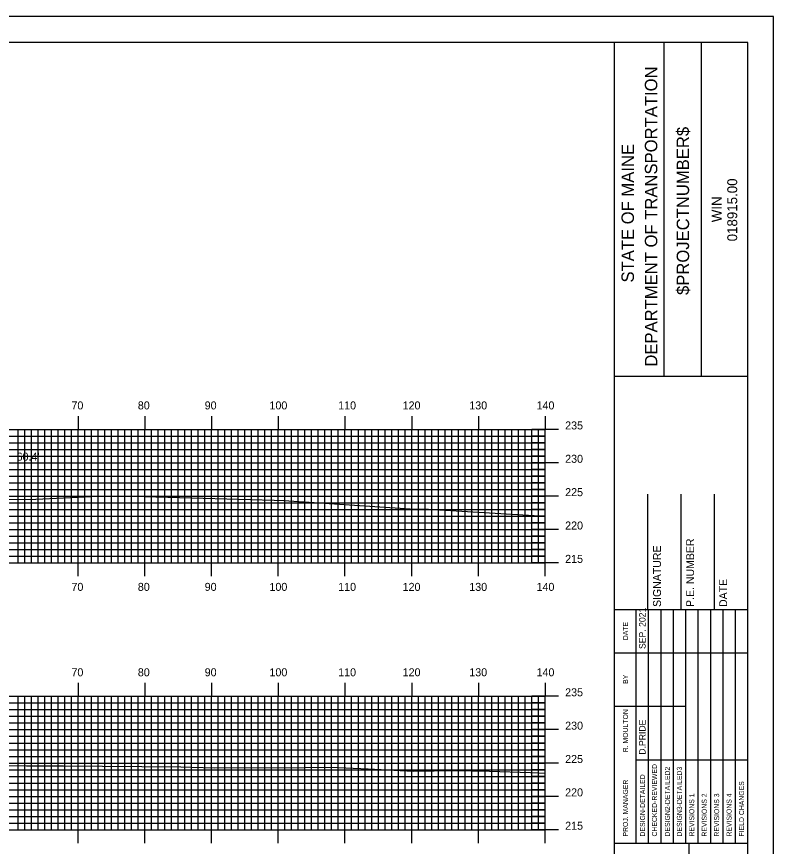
# Model space of a CAD drawing. Extents: x 1804684 to 1805027, y 442591 to 442811.
# Drawn here: x 1804910.5 to 1805023.9, y 442686.2 to 442810.5 of the extents above; entities that cross this region are included whole.
import ezdxf

# ---------------------------------------------------------------- set-up
doc = ezdxf.new("R2010")
doc.units = 0
for name, color, linetype in [('BORDER', 7, 'Continuous'), ('D_Text_Standard', 7, 'Continuous'), ('H_V ANNOTATION', 7, 'Continuous'), ('MAJOR', 7, 'Continuous'), ('MINOR', 7, 'Continuous'), ('PLOT BOUNDARY', 7, 'Continuous'), ('S_Roadway_Centerline', 7, 'Continuous')]:
    doc.layers.add(name, color=color, linetype=linetype)

msp = doc.modelspace()

# ---------------------------------------------------------------- linework, layer by layer
at = {"layer": 'BORDER'}
for p, q in [((1805000.08, 442596.67), (1805000.08, 442806.67)), ((1805007.54, 442756.66), (1805007.54, 442806.66)), ((1805013.13, 442756.66), (1805013.13, 442806.66)), ((1805000.08, 442756.65), (1805020.08, 442756.65)), ((1805005.08, 442721.67), (1805005.08, 442738.97)), ((1805010.08, 442721.67), (1805010.08, 442738.97)), ((1805015.08, 442721.67), (1805015.08, 442738.97)), ((1805000.08, 442721.67), (1805020.08, 442721.67)), ((1805000.08, 442686.67), (1805020.08, 442686.67)), ((1805011.26, 442616.67), (1805011.26, 442686.67))]:
    msp.add_line(p, q, dxfattribs=at)
msp.add_lwpolyline([(1804700.08, 442596.67), (1805020.08, 442596.67), (1805020.08, 442806.67), (1804700.08, 442806.67)], close=True, dxfattribs=at)
for points in [[(1805003.31, 442715.17), (1805003.31, 442721.67)], [(1805005.18, 442686.68), (1805005.18, 442721.67)], [(1805007.04, 442721.67), (1805007.04, 442686.68)], [(1805008.9, 442686.68), (1805008.9, 442721.67)], [(1805010.77, 442686.68), (1805010.77, 442721.67)], [(1805012.63, 442686.68), (1805012.63, 442721.67)], [(1805014.49, 442686.68), (1805014.49, 442721.67)], [(1805016.36, 442686.68), (1805016.36, 442721.67)], [(1805018.22, 442686.68), (1805018.22, 442721.67)], [(1805003.31, 442686.68), (1805003.31, 442720.26)], [(1805000.08, 442715.17), (1805020.08, 442715.17)], [(1805000.08, 442707.17), (1805003.31, 442707.17)], [(1805003.31, 442707.17), (1805010.76, 442707.17)], [(1805003.31, 442699.17), (1805020.08, 442699.17)]]:
    msp.add_lwpolyline(points, dxfattribs=at)
at = {"layer": 'MAJOR'}
for p, q in [((1804919.68, 442750.67), (1804919.68, 442748.67)), ((1804929.68, 442750.67), (1804929.68, 442748.67)), ((1804939.68, 442750.67), (1804939.68, 442748.67)), ((1804949.68, 442750.67), (1804949.68, 442748.67)), ((1804959.68, 442750.67), (1804959.68, 442748.67)), ((1804969.68, 442750.67), (1804969.68, 442748.67)), ((1804979.68, 442750.67), (1804979.68, 442748.67)), ((1804989.68, 442750.67), (1804989.68, 442748.67)), ((1804709.68, 442748.67), (1804989.68, 442748.67)), ((1804709.68, 442748.67), (1804989.68, 442748.67)), ((1804919.68, 442728.67), (1804919.68, 442748.67)), ((1804929.68, 442728.67), (1804929.68, 442748.67)), ((1804939.68, 442728.67), (1804939.68, 442748.67)), ((1804949.68, 442728.67), (1804949.68, 442748.67)), ((1804959.68, 442728.67), (1804959.68, 442748.67)), ((1804969.68, 442728.67), (1804969.68, 442748.67)), ((1804979.68, 442728.67), (1804979.68, 442748.67)), ((1804991.68, 442748.67), (1804987.68, 442748.67)), ((1804989.68, 442728.67), (1804989.68, 442748.67)), ((1804989.68, 442728.67), (1804989.68, 442748.67)), ((1804709.68, 442743.67), (1804989.68, 442743.67)), ((1804991.68, 442743.67), (1804987.68, 442743.67)), ((1804709.68, 442738.67), (1804989.68, 442738.67)), ((1804991.68, 442738.67), (1804987.68, 442738.67)), ((1804709.68, 442733.67), (1804989.68, 442733.67)), ((1804991.68, 442733.67), (1804987.68, 442733.67)), ((1804709.68, 442728.67), (1804989.68, 442728.67)), ((1804709.68, 442728.67), (1804989.68, 442728.67)), ((1804919.68, 442726.66), (1804919.68, 442728.67)), ((1804929.68, 442726.66), (1804929.68, 442728.67)), ((1804939.68, 442726.66), (1804939.68, 442728.67)), ((1804949.68, 442726.66), (1804949.68, 442728.67)), ((1804959.68, 442726.66), (1804959.68, 442728.67)), ((1804969.68, 442726.66), (1804969.68, 442728.67)), ((1804979.68, 442726.66), (1804979.68, 442728.67)), ((1804991.68, 442728.67), (1804987.68, 442728.67)), ((1804989.68, 442726.66), (1804989.68, 442728.67)), ((1804919.68, 442710.67), (1804919.68, 442708.67)), ((1804929.68, 442710.67), (1804929.68, 442708.67)), ((1804939.68, 442710.67), (1804939.68, 442708.67)), ((1804949.68, 442710.67), (1804949.68, 442708.67)), ((1804959.68, 442710.67), (1804959.68, 442708.67)), ((1804969.68, 442710.67), (1804969.68, 442708.67)), ((1804979.68, 442710.67), (1804979.68, 442708.67)), ((1804989.68, 442710.67), (1804989.68, 442708.67)), ((1804709.68, 442708.67), (1804989.68, 442708.67)), ((1804709.68, 442708.67), (1804989.68, 442708.67)), ((1804919.68, 442688.67), (1804919.68, 442708.67)), ((1804929.68, 442688.67), (1804929.68, 442708.67)), ((1804939.68, 442688.67), (1804939.68, 442708.67)), ((1804949.68, 442688.67), (1804949.68, 442708.67)), ((1804959.68, 442688.67), (1804959.68, 442708.67)), ((1804969.68, 442688.67), (1804969.68, 442708.67)), ((1804979.68, 442688.67), (1804979.68, 442708.67)), ((1804991.68, 442708.67), (1804987.68, 442708.67)), ((1804989.68, 442688.67), (1804989.68, 442708.67)), ((1804989.68, 442688.67), (1804989.68, 442708.67)), ((1804709.68, 442703.67), (1804989.68, 442703.67)), ((1804991.68, 442703.67), (1804987.68, 442703.67)), ((1804709.68, 442698.67), (1804989.68, 442698.67)), ((1804991.68, 442698.67), (1804987.68, 442698.67)), ((1804709.68, 442693.67), (1804989.68, 442693.67)), ((1804991.68, 442693.67), (1804987.68, 442693.67)), ((1804709.68, 442688.67), (1804989.68, 442688.67)), ((1804709.68, 442688.67), (1804989.68, 442688.67)), ((1804919.68, 442686.66), (1804919.68, 442688.67)), ((1804929.68, 442686.66), (1804929.68, 442688.67)), ((1804939.68, 442686.66), (1804939.68, 442688.67)), ((1804949.68, 442686.66), (1804949.68, 442688.67)), ((1804959.68, 442686.66), (1804959.68, 442688.67)), ((1804969.68, 442686.66), (1804969.68, 442688.67)), ((1804979.68, 442686.66), (1804979.68, 442688.67)), ((1804991.68, 442688.67), (1804987.68, 442688.67)), ((1804989.68, 442686.66), (1804989.68, 442688.67))]:
    msp.add_line(p, q, dxfattribs=at)
at = {"layer": 'MINOR'}
for p, q in [((1804910.68, 442728.67), (1804910.68, 442748.67)), ((1804911.68, 442728.67), (1804911.68, 442748.67)), ((1804912.68, 442728.67), (1804912.68, 442748.67)), ((1804913.68, 442728.67), (1804913.68, 442748.67)), ((1804914.68, 442728.67), (1804914.68, 442748.67)), ((1804915.68, 442728.67), (1804915.68, 442748.67)), ((1804916.68, 442728.67), (1804916.68, 442748.67)), ((1804917.68, 442728.67), (1804917.68, 442748.67)), ((1804918.68, 442728.67), (1804918.68, 442748.67)), ((1804920.68, 442728.67), (1804920.68, 442748.67)), ((1804921.68, 442728.67), (1804921.68, 442748.67)), ((1804922.68, 442728.67), (1804922.68, 442748.67)), ((1804923.68, 442728.67), (1804923.68, 442748.67)), ((1804924.68, 442728.67), (1804924.68, 442748.67)), ((1804925.68, 442728.67), (1804925.68, 442748.67)), ((1804926.68, 442728.67), (1804926.68, 442748.67)), ((1804927.68, 442728.67), (1804927.68, 442748.67)), ((1804928.68, 442728.67), (1804928.68, 442748.67)), ((1804930.68, 442728.67), (1804930.68, 442748.67)), ((1804931.68, 442728.67), (1804931.68, 442748.67)), ((1804932.68, 442728.67), (1804932.68, 442748.67)), ((1804933.68, 442728.67), (1804933.68, 442748.67)), ((1804934.68, 442728.67), (1804934.68, 442748.67)), ((1804935.68, 442728.67), (1804935.68, 442748.67)), ((1804936.68, 442728.67), (1804936.68, 442748.67)), ((1804937.68, 442728.67), (1804937.68, 442748.67)), ((1804938.68, 442728.67), (1804938.68, 442748.67)), ((1804940.68, 442728.67), (1804940.68, 442748.67)), ((1804941.68, 442728.67), (1804941.68, 442748.67)), ((1804942.68, 442728.67), (1804942.68, 442748.67)), ((1804943.68, 442728.67), (1804943.68, 442748.67)), ((1804944.68, 442728.67), (1804944.68, 442748.67)), ((1804945.68, 442728.67), (1804945.68, 442748.67)), ((1804946.68, 442728.67), (1804946.68, 442748.67)), ((1804947.68, 442728.67), (1804947.68, 442748.67)), ((1804948.68, 442728.67), (1804948.68, 442748.67)), ((1804950.68, 442728.67), (1804950.68, 442748.67)), ((1804951.68, 442728.67), (1804951.68, 442748.67)), ((1804952.68, 442728.67), (1804952.68, 442748.67)), ((1804953.68, 442728.67), (1804953.68, 442748.67)), ((1804954.68, 442728.67), (1804954.68, 442748.67)), ((1804955.68, 442728.67), (1804955.68, 442748.67)), ((1804956.68, 442728.67), (1804956.68, 442748.67)), ((1804957.68, 442728.67), (1804957.68, 442748.67)), ((1804958.68, 442728.67), (1804958.68, 442748.67)), ((1804960.68, 442728.67), (1804960.68, 442748.67)), ((1804961.68, 442728.67), (1804961.68, 442748.67)), ((1804962.68, 442728.67), (1804962.68, 442748.67)), ((1804963.68, 442728.67), (1804963.68, 442748.67)), ((1804964.68, 442728.67), (1804964.68, 442748.67)), ((1804965.68, 442728.67), (1804965.68, 442748.67)), ((1804966.68, 442728.67), (1804966.68, 442748.67)), ((1804967.68, 442728.67), (1804967.68, 442748.67)), ((1804968.68, 442728.67), (1804968.68, 442748.67)), ((1804970.68, 442728.67), (1804970.68, 442748.67)), ((1804971.68, 442728.67), (1804971.68, 442748.67)), ((1804972.68, 442728.67), (1804972.68, 442748.67)), ((1804973.68, 442728.67), (1804973.68, 442748.67)), ((1804974.68, 442728.67), (1804974.68, 442748.67)), ((1804975.68, 442728.67), (1804975.68, 442748.67)), ((1804976.68, 442728.67), (1804976.68, 442748.67)), ((1804977.68, 442728.67), (1804977.68, 442748.67)), ((1804978.68, 442728.67), (1804978.68, 442748.67)), ((1804980.68, 442728.67), (1804980.68, 442748.67)), ((1804981.68, 442728.67), (1804981.68, 442748.67)), ((1804982.68, 442728.67), (1804982.68, 442748.67)), ((1804983.68, 442728.67), (1804983.68, 442748.67)), ((1804984.68, 442728.67), (1804984.68, 442748.67)), ((1804985.68, 442728.67), (1804985.68, 442748.67)), ((1804986.68, 442728.67), (1804986.68, 442748.67)), ((1804987.68, 442728.67), (1804987.68, 442748.67)), ((1804988.68, 442728.67), (1804988.68, 442748.67)), ((1804709.68, 442747.67), (1804989.68, 442747.67)), ((1804989.68, 442747.67), (1804987.68, 442747.67)), ((1804709.68, 442746.67), (1804989.68, 442746.67)), ((1804709.68, 442745.67), (1804989.68, 442745.67)), ((1804989.68, 442746.67), (1804987.68, 442746.67)), ((1804989.68, 442745.67), (1804987.68, 442745.67)), ((1804709.68, 442744.67), (1804989.68, 442744.67)), ((1804989.68, 442744.67), (1804987.68, 442744.67)), ((1804709.68, 442742.67), (1804989.68, 442742.67)), ((1804989.68, 442742.67), (1804987.68, 442742.67)), ((1804709.68, 442741.67), (1804989.68, 442741.67)), ((1804709.68, 442740.67), (1804989.68, 442740.67)), ((1804989.68, 442741.67), (1804987.68, 442741.67)), ((1804989.68, 442740.67), (1804987.68, 442740.67)), ((1804709.68, 442739.67), (1804989.68, 442739.67)), ((1804989.68, 442739.67), (1804987.68, 442739.67)), ((1804709.68, 442737.67), (1804989.68, 442737.67)), ((1804989.68, 442737.67), (1804987.68, 442737.67)), ((1804709.68, 442736.67), (1804989.68, 442736.67)), ((1804709.68, 442735.67), (1804989.68, 442735.67)), ((1804989.68, 442736.67), (1804987.68, 442736.67)), ((1804989.68, 442735.67), (1804987.68, 442735.67)), ((1804709.68, 442734.67), (1804989.68, 442734.67)), ((1804989.68, 442734.67), (1804987.68, 442734.67)), ((1804709.68, 442732.67), (1804989.68, 442732.67)), ((1804989.68, 442732.67), (1804987.68, 442732.67)), ((1804709.68, 442731.67), (1804989.68, 442731.67)), ((1804709.68, 442730.67), (1804989.68, 442730.67)), ((1804989.68, 442731.67), (1804987.68, 442731.67)), ((1804989.68, 442730.67), (1804987.68, 442730.67)), ((1804709.68, 442729.67), (1804989.68, 442729.67)), ((1804989.68, 442729.67), (1804987.68, 442729.67)), ((1804910.68, 442688.67), (1804910.68, 442708.67)), ((1804911.68, 442688.67), (1804911.68, 442708.67)), ((1804912.68, 442688.67), (1804912.68, 442708.67)), ((1804913.68, 442688.67), (1804913.68, 442708.67)), ((1804914.68, 442688.67), (1804914.68, 442708.67)), ((1804915.68, 442688.67), (1804915.68, 442708.67)), ((1804916.68, 442688.67), (1804916.68, 442708.67)), ((1804917.68, 442688.67), (1804917.68, 442708.67)), ((1804918.68, 442688.67), (1804918.68, 442708.67)), ((1804920.68, 442688.67), (1804920.68, 442708.67)), ((1804921.68, 442688.67), (1804921.68, 442708.67)), ((1804922.68, 442688.67), (1804922.68, 442708.67)), ((1804923.68, 442688.67), (1804923.68, 442708.67)), ((1804924.68, 442688.67), (1804924.68, 442708.67)), ((1804925.68, 442688.67), (1804925.68, 442708.67)), ((1804926.68, 442688.67), (1804926.68, 442708.67)), ((1804927.68, 442688.67), (1804927.68, 442708.67)), ((1804928.68, 442688.67), (1804928.68, 442708.67)), ((1804930.68, 442688.67), (1804930.68, 442708.67)), ((1804931.68, 442688.67), (1804931.68, 442708.67)), ((1804932.68, 442688.67), (1804932.68, 442708.67)), ((1804933.68, 442688.67), (1804933.68, 442708.67)), ((1804934.68, 442688.67), (1804934.68, 442708.67)), ((1804935.68, 442688.67), (1804935.68, 442708.67)), ((1804936.68, 442688.67), (1804936.68, 442708.67)), ((1804937.68, 442688.67), (1804937.68, 442708.67)), ((1804938.68, 442688.67), (1804938.68, 442708.67)), ((1804940.68, 442688.67), (1804940.68, 442708.67)), ((1804941.68, 442688.67), (1804941.68, 442708.67)), ((1804942.68, 442688.67), (1804942.68, 442708.67)), ((1804943.68, 442688.67), (1804943.68, 442708.67)), ((1804944.68, 442688.67), (1804944.68, 442708.67)), ((1804945.68, 442688.67), (1804945.68, 442708.67)), ((1804946.68, 442688.67), (1804946.68, 442708.67)), ((1804947.68, 442688.67), (1804947.68, 442708.67)), ((1804948.68, 442688.67), (1804948.68, 442708.67)), ((1804950.68, 442688.67), (1804950.68, 442708.67)), ((1804951.68, 442688.67), (1804951.68, 442708.67)), ((1804952.68, 442688.67), (1804952.68, 442708.67)), ((1804953.68, 442688.67), (1804953.68, 442708.67)), ((1804954.68, 442688.67), (1804954.68, 442708.67)), ((1804955.68, 442688.67), (1804955.68, 442708.67)), ((1804956.68, 442688.67), (1804956.68, 442708.67)), ((1804957.68, 442688.67), (1804957.68, 442708.67)), ((1804958.68, 442688.67), (1804958.68, 442708.67)), ((1804960.68, 442688.67), (1804960.68, 442708.67)), ((1804961.68, 442688.67), (1804961.68, 442708.67)), ((1804962.68, 442688.67), (1804962.68, 442708.67)), ((1804963.68, 442688.67), (1804963.68, 442708.67)), ((1804964.68, 442688.67), (1804964.68, 442708.67)), ((1804965.68, 442688.67), (1804965.68, 442708.67)), ((1804966.68, 442688.67), (1804966.68, 442708.67)), ((1804967.68, 442688.67), (1804967.68, 442708.67)), ((1804968.68, 442688.67), (1804968.68, 442708.67)), ((1804970.68, 442688.67), (1804970.68, 442708.67)), ((1804971.68, 442688.67), (1804971.68, 442708.67)), ((1804972.68, 442688.67), (1804972.68, 442708.67)), ((1804973.68, 442688.67), (1804973.68, 442708.67)), ((1804974.68, 442688.67), (1804974.68, 442708.67)), ((1804975.68, 442688.67), (1804975.68, 442708.67)), ((1804976.68, 442688.67), (1804976.68, 442708.67)), ((1804977.68, 442688.67), (1804977.68, 442708.67)), ((1804978.68, 442688.67), (1804978.68, 442708.67)), ((1804980.68, 442688.67), (1804980.68, 442708.67)), ((1804981.68, 442688.67), (1804981.68, 442708.67)), ((1804982.68, 442688.67), (1804982.68, 442708.67)), ((1804983.68, 442688.67), (1804983.68, 442708.67)), ((1804984.68, 442688.67), (1804984.68, 442708.67)), ((1804985.68, 442688.67), (1804985.68, 442708.67)), ((1804986.68, 442688.67), (1804986.68, 442708.67)), ((1804987.68, 442688.67), (1804987.68, 442708.67)), ((1804988.68, 442688.67), (1804988.68, 442708.67)), ((1804709.68, 442707.67), (1804989.68, 442707.67)), ((1804989.68, 442707.67), (1804987.68, 442707.67)), ((1804709.68, 442706.67), (1804989.68, 442706.67)), ((1804989.68, 442706.67), (1804987.68, 442706.67)), ((1804709.68, 442705.67), (1804989.68, 442705.67)), ((1804709.68, 442704.67), (1804989.68, 442704.67)), ((1804989.68, 442705.67), (1804987.68, 442705.67)), ((1804989.68, 442704.67), (1804987.68, 442704.67)), ((1804709.68, 442702.67), (1804989.68, 442702.67)), ((1804989.68, 442702.67), (1804987.68, 442702.67)), ((1804709.68, 442701.67), (1804989.68, 442701.67)), ((1804989.68, 442701.67), (1804987.68, 442701.67)), ((1804709.68, 442700.67), (1804989.68, 442700.67)), ((1804709.68, 442699.67), (1804989.68, 442699.67)), ((1804989.68, 442700.67), (1804987.68, 442700.67)), ((1804989.68, 442699.67), (1804987.68, 442699.67)), ((1804709.68, 442697.67), (1804989.68, 442697.67)), ((1804989.68, 442697.67), (1804987.68, 442697.67)), ((1804709.68, 442696.67), (1804989.68, 442696.67)), ((1804989.68, 442696.67), (1804987.68, 442696.67)), ((1804709.68, 442695.67), (1804989.68, 442695.67)), ((1804709.68, 442694.67), (1804989.68, 442694.67)), ((1804989.68, 442695.67), (1804987.68, 442695.67)), ((1804989.68, 442694.67), (1804987.68, 442694.67)), ((1804709.68, 442692.67), (1804989.68, 442692.67)), ((1804989.68, 442692.67), (1804987.68, 442692.67)), ((1804709.68, 442691.67), (1804989.68, 442691.67)), ((1804989.68, 442691.67), (1804987.68, 442691.67)), ((1804709.68, 442690.67), (1804989.68, 442690.67)), ((1804709.68, 442689.67), (1804989.68, 442689.67)), ((1804989.68, 442690.67), (1804987.68, 442690.67)), ((1804989.68, 442689.67), (1804987.68, 442689.67))]:
    msp.add_line(p, q, dxfattribs=at)
at = {"layer": 'PLOT BOUNDARY'}
msp.add_lwpolyline([(1804683.89, 442590.55), (1805023.89, 442590.55), (1805023.89, 442810.55), (1804683.89, 442810.55)], close=True, dxfattribs=at)
at = {"layer": 'S_Roadway_Centerline'}
for points in [[(1804903.66, 442738.19), (1804913.35, 442738.24), (1804921.64, 442738.64), (1804924.64, 442738.7), (1804927.76, 442738.68), (1804949.04, 442738.07), (1804950.5, 442738.01), (1804969.43, 442736.76), (1804972.2, 442736.71), (1804989.68, 442735.69)], [(1804906.83, 442698.3), (1804911.96, 442698.24), (1804917.47, 442698.23), (1804935.06, 442698.09), (1804940.07, 442697.96), (1804953.63, 442697.99), (1804957.58, 442698.03), (1804963.17, 442697.79), (1804969.91, 442697.44), (1804976.22, 442697.54), (1804981.32, 442697.45), (1804987.49, 442697.25), (1804989.68, 442697.16)]]:
    msp.add_lwpolyline(points, dxfattribs=at)

# ---------------------------------------------------------------- texts
at = {"layer": 'BORDER'}
for s, height, p in [('DEPARTMENT OF TRANSPORTATION', 1.8635, (1805006.49, 442758.08)), ('$PROJECTNUMBER$', 1.8635, (1805011.26, 442768.82)), ('STATE OF MAINE', 1.8635, (1805002.99, 442770.69)), ('018915.00', 1.491, (1805018.47, 442776.86)), ('WIN', 1.491, (1805016.15, 442779.73)), ('P.E. NUMBER', 1.1811, (1805012, 442722.06)), ('SIGNATURE', 1.181, (1805007.04, 442722.06)), ('DATE', 1.181, (1805016.96, 442722.06)), ('SEP. 2021', 0.969, (1805004.73, 442715.76)), ('DATE', 0.743, (1805002.09, 442717.08)), ('BY', 0.743, (1805002.09, 442710.54)), ('R. MOULTON', 0.745, (1805002.09, 442700.28)), ('D.PRIDE', 0.969, (1805004.73, 442699.92)), ('CHECKED-REVIEWED', 0.7455, (1805006.44, 442687.65)), ('DESIGN2-DETAILED2', 0.7455, (1805008.38, 442687.65)), ('DESIGN3-DETAILED3', 0.7455, (1805010.17, 442687.65)), ('PROJ. MANAGER', 0.7455, (1805002.09, 442687.65)), ('DESIGN-DETAILED', 0.7455, (1805004.65, 442687.65)), ('FIELD CHANGES', 0.7455, (1805019.49, 442687.65)), ('REVISIONS 1', 0.7455, (1805012.03, 442687.65)), ('REVISIONS 2', 0.7455, (1805013.9, 442687.65)), ('REVISIONS 3', 0.7455, (1805015.76, 442687.65)), ('REVISIONS 4', 0.7455, (1805017.62, 442687.65))]:
    msp.add_text(s, height=height, rotation=90, dxfattribs=at).set_placement(p)
at = {"layer": 'D_Text_Standard'}
msp.add_text("60.4'", height=1.2, dxfattribs=at).set_placement((1804910.46, 442743.99))
at = {"layer": 'H_V ANNOTATION'}
for s, p in [('70', (1804918.68, 442751.67)), ('80', (1804928.63, 442751.67)), ('90', (1804938.65, 442751.67)), ('100', (1804948.36, 442751.67)), ('110', (1804958.66, 442751.67)), ('120', (1804968.32, 442751.67)), ('130', (1804978.31, 442751.67)), ('140', (1804988.39, 442751.67)), ('235', (1804992.68, 442748.67)), ('230', (1804992.68, 442743.67)), ('225', (1804992.68, 442738.67)), ('220', (1804992.68, 442733.67)), ('215', (1804992.68, 442728.67)), ('70', (1804918.68, 442724.47)), ('80', (1804928.63, 442724.47)), ('90', (1804938.65, 442724.47)), ('100', (1804948.36, 442724.47)), ('110', (1804958.66, 442724.47)), ('120', (1804968.32, 442724.47)), ('130', (1804978.31, 442724.47)), ('140', (1804988.39, 442724.47)), ('70', (1804918.68, 442711.67)), ('80', (1804928.63, 442711.67)), ('90', (1804938.65, 442711.67)), ('100', (1804948.36, 442711.67)), ('110', (1804958.66, 442711.67)), ('120', (1804968.32, 442711.67)), ('130', (1804978.31, 442711.67)), ('140', (1804988.39, 442711.67)), ('235', (1804992.68, 442708.67)), ('230', (1804992.68, 442703.67)), ('225', (1804992.68, 442698.67)), ('220', (1804992.68, 442693.67)), ('215', (1804992.68, 442688.67))]:
    msp.add_text(s, height=1.2, dxfattribs=at).set_placement(p)

doc.saveas('drawing.dxf')
